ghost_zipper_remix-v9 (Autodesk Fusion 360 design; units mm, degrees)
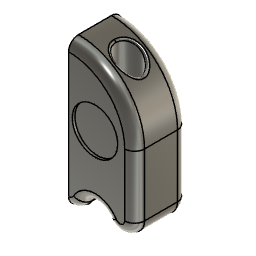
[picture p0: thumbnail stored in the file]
parameter "cord_d" = 6
parameter "knot_d" = 10
parameter "magnet_d" = 3.1
parameter "magnet_h" = 2.4
parameter "eye_d" = 11
base_feature "Base Feature1"
place_component sketch "Sketch3"
copy_paste_bodies "CutPasteBodies" sketch "Sketch3"
sketch "Sketch1" plane through (0, 0, 0) normal (0, 1, 0) x axis (1, 0, 0)
  line L1 (0, 24) -> (0, -20)
  line L2 (20, 18.886) -> (20, 0)
  arc A1 centre (0, 0) radius 20 clockwise from (20, 0) to (0, -20)
  arc A2 centre (15.574, 18.934) radius 4.4262 clockwise from (11.8998, 21.4021) to (20, 18.886)
  arc A3 centre (8.0581, 23.608) radius 4.4299 clockwise from (11.8998, 21.4021) to (4.1578, 21.5075)
  arc A4 centre (-0.0156, 19.2598) radius 4.7402 clockwise from (0, 24) to (4.1578, 21.5075)
  point P2 (0, -20)
  point P6 (0, -20)
  point P3 (0, 24)
  point P7 (0, 24)
  point P4 (20, 0)
  point P10 (20, 0)
  point P9 (0, -20)
  point P11 (20, 0)
  point P5 (20, 18.886)
  point P12 (20, 18.886)
  point P13 (16.5472, 23.2519)
  point P14 (11.8998, 21.4021)
  point P15 (11.8998, 21.4021)
  point P17 (4.1578, 21.5075)
  point P18 (4.1578, 21.5075)
  point P20 (2.2947, 23.3989)
  point P21 (4.1578, 21.5075)
  coincident P2 P6
  coincident P3 P7
  coincident P4 P10
  coincident P2 P9
  coincident P4 P11
  coincident P5 P12
  coincident P13 A2
  coincident P14 P15
  coincident P17 P18
  coincident P20 A4
  coincident P17 P21
  tangent A3 A4
  tangent A1 L2
extrude "Extrude1" new body sketch "Sketch1" distance -8
fillet "Fillet1" radius 3
sketch "Sketch2" plane through (0, 8, 0) normal (0, 1, 0) x axis (-1, 0, 0)
  line L1 (-17, -18.9067) -> (-17, 0)
  line L2 (0, 17) -> (0, -21)
  line L3 (-12.6729, 6.151) -> (-7.9776, 1.5746)
  line L4 (-14.0689, 4.7187) -> (-12.6729, 6.151)
  line L5 (-9.4571, 0.2238) -> (-14.0689, 4.7187)
  line L6 (-14.213, -4.1184) -> (-9.4571, 0.2238)
  line L7 (-7.9776, 1.5746) -> (-3.1355, 5.9954)
  line L8 (-3.1355, 5.9954) -> (-1.787, 4.5184)
  line L9 (-1.787, 4.5184) -> (-6.5429, 0.1762)
  line L10 (-6.5429, 0.1762) -> (-1.9311, -4.3187)
  line L11 (-1.9311, -4.3187) -> (-3.3271, -5.751)
  line L12 (-3.3271, -5.751) -> (-8.0224, -1.1746)
  line L13 (-8.0224, -1.1746) -> (-12.8645, -5.5954)
  line L14 (-12.8645, -5.5954) -> (-14.213, -4.1184)
  arc A1 centre (0, 0) radius 17 clockwise from (-17, 0) to (0, 17)
  arc A2 centre (-15.574, -18.934) radius 1.4262 clockwise from (-14.4271, -19.7818) to (-17, -18.9067)
  arc A3 centre (-8.0581, -23.608) radius 7.4299 clockwise from (-14.4271, -19.7818) to (-1.5165, -20.0849)
  arc A4 centre (0.0156, -19.2598) radius 1.7402 clockwise from (0, -21) to (-1.5165, -20.0849)
extrude "Extrude2" cut sketch "Sketch2" profile of L3 L4 L5 L6 L7 L8 L9 L10 L11 L12 L13 L14 against normal blind 0.8
sketch "Sketch3" plane through (0, -8, 0) normal (0, -1, 0) x axis (1, 0, 0)
  line L1 (0, -21) -> (0, 17)
  line L2 (17, 0) -> (17, -18.9022)
  line L3 (1.7, 0.2) -> (1.7101, 0.5564)
  line L4 (1.7101, -0.1564) -> (1.7, 0.2)
  line L5 (1.7403, -0.5117) -> (1.7101, -0.1564)
  line L6 (1.7906, -0.8647) -> (1.7403, -0.5117)
  line L7 (1.8608, -1.2143) -> (1.7906, -0.8647)
  line L8 (1.9506, -1.5594) -> (1.8608, -1.2143)
  line L9 (2.0599, -1.8988) -> (1.9506, -1.5594)
  line L10 (2.1881, -2.2315) -> (2.0599, -1.8988)
  line L11 (2.335, -2.5564) -> (2.1881, -2.2315)
  line L12 (2.5, -2.8725) -> (2.335, -2.5564)
  line L13 (2.6826, -3.1787) -> (2.5, -2.8725)
  line L14 (2.8823, -3.4741) -> (2.6826, -3.1787)
  line L15 (3.0984, -3.7578) -> (2.8823, -3.4741)
  line L16 (3.3301, -4.0288) -> (3.0984, -3.7578)
  line L17 (3.5769, -4.2862) -> (3.3301, -4.0288)
  line L18 (3.8377, -4.5292) -> (3.5769, -4.2862)
  line L19 (4.112, -4.7571) -> (3.8377, -4.5292)
  line L20 (4.3987, -4.9692) -> (4.112, -4.7571)
  line L21 (4.6969, -5.1646) -> (4.3987, -4.9692)
  line L22 (5.0057, -5.3429) -> (4.6969, -5.1646)
  line L23 (5.324, -5.5034) -> (5.0057, -5.3429)
  line L24 (5.651, -5.6457) -> (5.324, -5.5034)
  line L25 (5.9855, -5.7692) -> (5.651, -5.6457)
  line L26 (6.3264, -5.8736) -> (5.9855, -5.7692)
  line L27 (6.6727, -5.9586) -> (6.3264, -5.8736)
  line L28 (7.0233, -6.0238) -> (6.6727, -5.9586)
  line L29 (7.3769, -6.0691) -> (7.0233, -6.0238)
  line L30 (7.7326, -6.0943) -> (7.3769, -6.0691)
  line L31 (8.0892, -6.0994) -> (7.7326, -6.0943)
  line L32 (8.4454, -6.0842) -> (8.0892, -6.0994)
  line L33 (8.8002, -6.049) -> (8.4454, -6.0842)
  line L34 (9.1525, -5.9937) -> (8.8002, -6.049)
  line L35 (9.501, -5.9186) -> (9.1525, -5.9937)
  line L36 (9.8448, -5.8239) -> (9.501, -5.9186)
  line L37 (10.1826, -5.7098) -> (9.8448, -5.8239)
  line L38 (10.5135, -5.5769) -> (10.1826, -5.7098)
  line L39 (10.8363, -5.4254) -> (10.5135, -5.5769)
  line L40 (11.15, -5.256) -> (10.8363, -5.4254)
  line L41 (11.4536, -5.069) -> (11.15, -5.256)
  line L42 (11.7462, -4.8652) -> (11.4536, -5.069)
  line L43 (12.0268, -4.6451) -> (11.7462, -4.8652)
  line L44 (12.2944, -4.4096) -> (12.0268, -4.6451)
  line L45 (12.5483, -4.1592) -> (12.2944, -4.4096)
  line L46 (12.7877, -3.8949) -> (12.5483, -4.1592)
  line L47 (13.0117, -3.6175) -> (12.7877, -3.8949)
  line L48 (13.2196, -3.3278) -> (13.0117, -3.6175)
  line L49 (13.4108, -3.0269) -> (13.2196, -3.3278)
  line L50 (13.5847, -2.7156) -> (13.4108, -3.0269)
  line L51 (13.7407, -2.395) -> (13.5847, -2.7156)
  line L52 (13.8784, -2.066) -> (13.7407, -2.395)
  line L53 (13.9971, -1.7298) -> (13.8784, -2.066)
  line L54 (14.0967, -1.3875) -> (13.9971, -1.7298)
  line L55 (14.1768, -1.04) -> (14.0967, -1.3875)
  line L56 (14.237, -0.6886) -> (14.1768, -1.04)
  line L57 (14.2773, -0.3343) -> (14.237, -0.6886)
  line L58 (14.2975, 0.0217) -> (14.2773, -0.3343)
  line L59 (14.2975, 0.3783) -> (14.2975, 0.0217)
  line L60 (14.2773, 0.7343) -> (14.2975, 0.3783)
  line L61 (14.237, 1.0886) -> (14.2773, 0.7343)
  line L62 (14.1768, 1.44) -> (14.237, 1.0886)
  line L63 (14.0967, 1.7875) -> (14.1768, 1.44)
  line L64 (13.9971, 2.1298) -> (14.0967, 1.7875)
  line L65 (13.8784, 2.466) -> (13.9971, 2.1298)
  line L66 (13.7407, 2.795) -> (13.8784, 2.466)
  line L67 (13.5847, 3.1156) -> (13.7407, 2.795)
  line L68 (13.4108, 3.4269) -> (13.5847, 3.1156)
  line L69 (13.2196, 3.7278) -> (13.4108, 3.4269)
  line L70 (13.0117, 4.0175) -> (13.2196, 3.7278)
  line L71 (12.7877, 4.2949) -> (13.0117, 4.0175)
  line L72 (12.5483, 4.5592) -> (12.7877, 4.2949)
  line L73 (12.2944, 4.8096) -> (12.5483, 4.5592)
  line L74 (12.0268, 5.0451) -> (12.2944, 4.8096)
  line L75 (11.7462, 5.2652) -> (12.0268, 5.0451)
  line L76 (11.4536, 5.469) -> (11.7462, 5.2652)
  line L77 (11.15, 5.656) -> (11.4536, 5.469)
  line L78 (10.8363, 5.8254) -> (11.15, 5.656)
  line L79 (10.5135, 5.9769) -> (10.8363, 5.8254)
  line L80 (10.1826, 6.1098) -> (10.5135, 5.9769)
  line L81 (9.8448, 6.2239) -> (10.1826, 6.1098)
  line L82 (9.501, 6.3186) -> (9.8448, 6.2239)
  line L83 (9.1525, 6.3937) -> (9.501, 6.3186)
  line L84 (8.8002, 6.449) -> (9.1525, 6.3937)
  line L85 (8.4454, 6.4842) -> (8.8002, 6.449)
  line L86 (8.0892, 6.4994) -> (8.4454, 6.4842)
  line L87 (7.7326, 6.4943) -> (8.0892, 6.4994)
  line L88 (7.3769, 6.4691) -> (7.7326, 6.4943)
  line L89 (7.0233, 6.4238) -> (7.3769, 6.4691)
  line L90 (6.6727, 6.3586) -> (7.0233, 6.4238)
  line L91 (6.3264, 6.2736) -> (6.6727, 6.3586)
  line L92 (5.9855, 6.1692) -> (6.3264, 6.2736)
  line L93 (5.651, 6.0457) -> (5.9855, 6.1692)
  line L94 (5.324, 5.9034) -> (5.651, 6.0457)
  line L95 (5.0057, 5.7429) -> (5.324, 5.9034)
  line L96 (4.6969, 5.5646) -> (5.0057, 5.7429)
  line L97 (4.3987, 5.3692) -> (4.6969, 5.5646)
  line L98 (4.112, 5.1571) -> (4.3987, 5.3692)
  line L99 (3.8377, 4.9292) -> (4.112, 5.1571)
  line L100 (3.5769, 4.6862) -> (3.8377, 4.9292)
  line L101 (3.3301, 4.4288) -> (3.5769, 4.6862)
  line L102 (3.0984, 4.1578) -> (3.3301, 4.4288)
  line L103 (2.8823, 3.8741) -> (3.0984, 4.1578)
  line L104 (2.6826, 3.5787) -> (2.8823, 3.8741)
  line L105 (2.5, 3.2725) -> (2.6826, 3.5787)
  line L106 (2.335, 2.9564) -> (2.5, 3.2725)
  line L107 (2.1881, 2.6315) -> (2.335, 2.9564)
  line L108 (2.0599, 2.2988) -> (2.1881, 2.6315)
  line L109 (1.9506, 1.9594) -> (2.0599, 2.2988)
  line L110 (1.8608, 1.6143) -> (1.9506, 1.9594)
  line L111 (1.7906, 1.2647) -> (1.8608, 1.6143)
  line L112 (1.7403, 0.9117) -> (1.7906, 1.2647)
  line L113 (1.7101, 0.5564) -> (1.7403, 0.9117)
  arc A1 centre (0, 0) radius 17 clockwise from (0, 17) to (17, 0)
  arc A2 centre (-0.0156, -19.2598) radius 1.7402 clockwise from (1.5165, -20.0849) to (0, -21)
  arc A3 centre (8.0581, -23.608) radius 7.4299 clockwise from (1.5165, -20.0849) to (14.4271, -19.7818)
  arc A4 centre (15.574, -18.934) radius 1.4262 clockwise from (16.9999, -18.9022) to (14.4271, -19.7818)
  circle C1 centre (8, 0.2) radius 6.3
  point P116 (2.5, 3.2725)
  point P86 (11.7462, 5.2652)
  point P64 (13.9971, -1.7298)
  coincident P116 C1
  coincident P86 C1
  coincident P64 C1
extrude "Extrude1" cut sketch "Sketch3" profile of C1 against normal blind 0.8
scale "Scale1" ScaleFactor 0.8
work_plane "WorkPlane1" AlongDistance 4
sketch "Sketch4" plane through (0, 0, 4) normal (0, 0, 1) x axis (1, 0, 0)
  line L1 (22.5, 0) -> (1.75, 0)
  circle C1 centre (8, 0) radius 5
  circle C2 centre (8, 0) radius 3
  point P2 (8, 0)
  point P1 (0, 0)
  point P3 (8, 0)
  concentric C1 C2
  coincident P2 L1
  dimension "d15" diameter C1 = 10 (= "knot_d")
  dimension "d16" diameter C2 = 6 (= "cord_d")
  dimension "d17" distance P1 P3 = 8
extrude "Extrude4" cut sketch "Sketch4" profile of C2 no distance stored
extrude "Extrude5" cut sketch "Sketch4" profile of C1 C2 no distance stored
fillet "Fillet2" radius 0.5
sketch "Sketch5" plane through (0, 0, 0) normal (-1, 0, 0) x axis (0, -1, 0)
  line L1 (-6.4, -16.8) -> (-6.4, 13.6)
  curve K1 (-6.4, -16.8) -> (-4, -19.2)
  line L2 (4, -19.2) -> (-4, -19.2)
  curve K2 (4, -19.2) -> (6.4, -16.8)
  line L3 (6.4, 13.6) -> (6.4, -16.8)
  line L4 (-4, 16) -> (4, 16)
  line L5 (0, -19.2) -> (0, 16)
  line L6 (6.4, -1.6) -> (-6.4, -1.6)
  arc A1 centre (-4, 13.6) radius 2.4 clockwise from (-6.4, 13.6) to (-4, 16)
  arc A2 centre (4, 13.6) radius 2.4 clockwise from (4, 16) to (6.4, 13.6)
  circle C1 centre (0, 8) radius 1.55
  circle C2 centre (0, -11.2) radius 1.55
  point P12 (0, 16)
  point P13 (0, -19.2)
  point P14 (-6.4, -1.6)
  point P15 (6.4, -1.6)
  point P16 (0, 8)
  midpoint L4 P12
  midpoint L2 P13
  midpoint L1 P14
  midpoint L3 P15
  coincident L5 P16
  symmetric L6 C1 C2
  dimension "d27" diameter C1 = 3.1 (= "magnet_d")
  dimension "d28" distance L4 P16 = 8
extrude "Extrude6" cut sketch "Sketch5" profile of C1 C2 no distance stored
chamfer "Chamfer1" distance 0.5
sketch "Sketch2" plane through (0, -6.4, 0) normal (0, -1, 0) x axis (1, 0, 0)
  line L1 (0, -16.8) -> (0, 13.6)
  line L2 (13.6, 0) -> (13.6, -15.1218)
  circle C1 centre (6.4, 0.16) radius 5.04
  arc A1 centre (0, 0) radius 13.6 clockwise from (0, 13.6) to (13.6, 0)
  arc A2 centre (-0.0125, -15.4078) radius 1.3922 clockwise from (1.2132, -16.068) to (0, -16.8)
  arc A3 centre (6.4465, -18.8864) radius 5.944 clockwise from (1.2132, -16.068) to (11.5417, -15.8254)
  arc A4 centre (12.4592, -15.1472) radius 1.141 clockwise from (13.5999, -15.1218) to (11.5417, -15.8254)
  circle C2 centre (6.4, 0.16) radius 5.5
  concentric C1 C2
  dimension "d36" diameter C2 = 11 (= "eye_d")
extrude "Extrude7" cut sketch "Sketch2" profile of C1 C2 to an object
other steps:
base_feature "Base Feature1" sketch "Sketch3"
extrude "Extrude3" cut sketch "Sketch3" profile of C1 against normal blind 0.8
create_component "CreateComponent2" sketch "Sketch3"
remove_body "RemoveBody1"
create_component "CreateComponent3"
